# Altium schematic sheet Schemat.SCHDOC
size A4
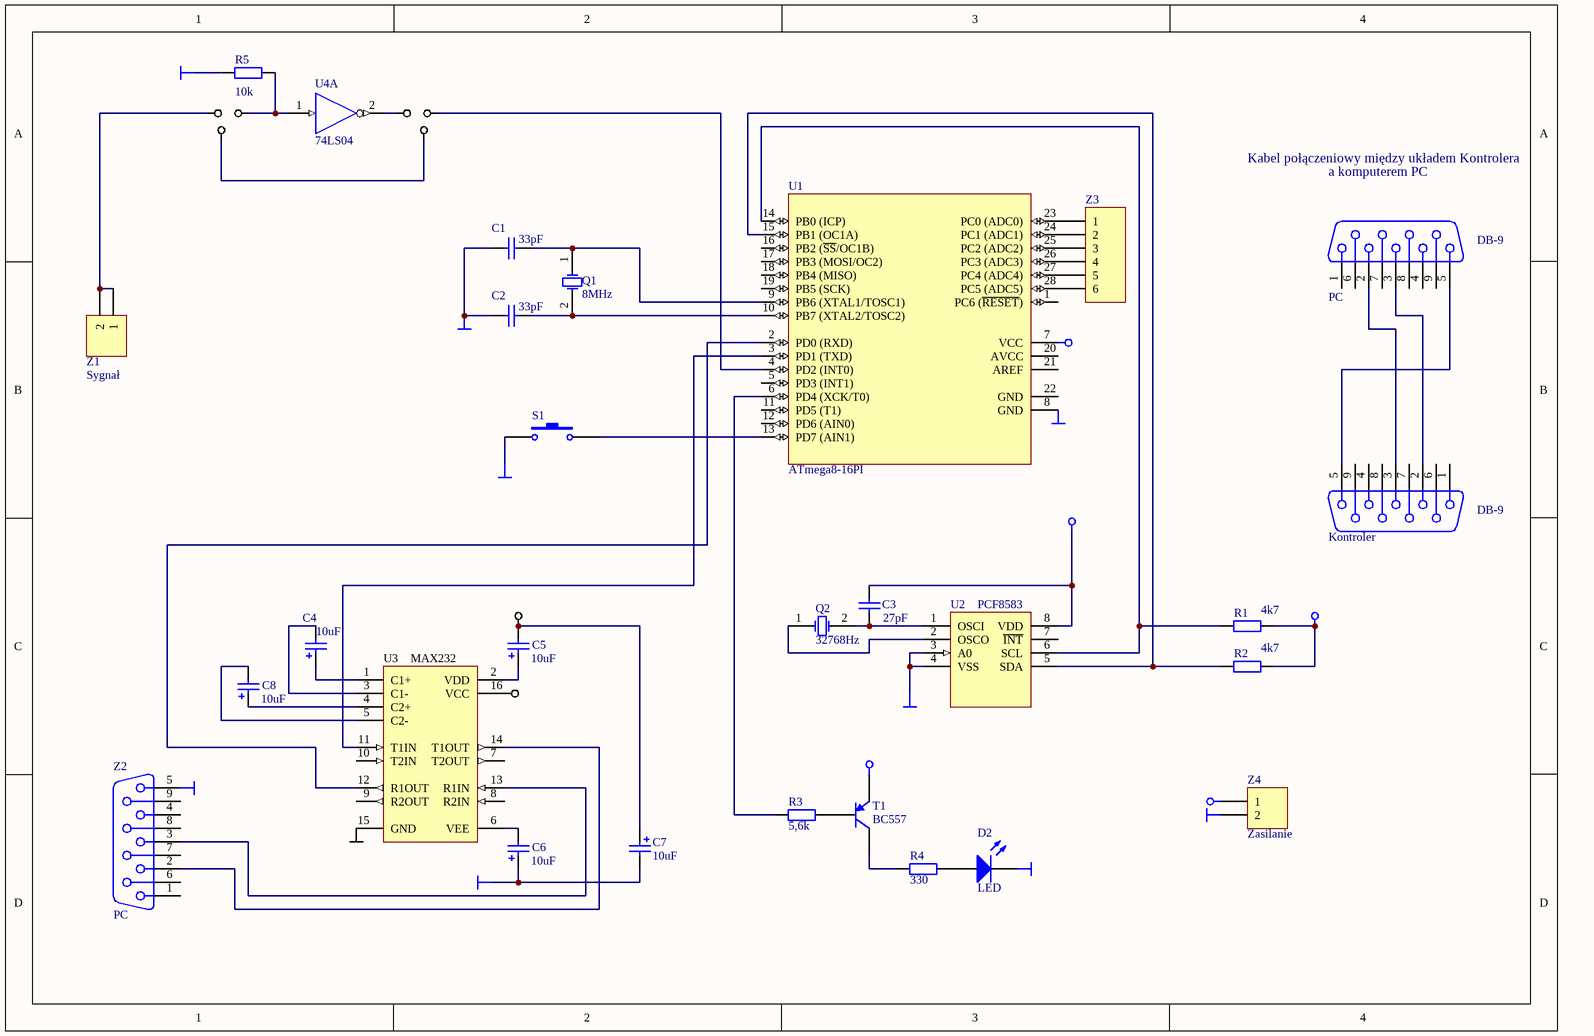
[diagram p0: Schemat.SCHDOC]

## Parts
(Parts that share a designator on the sheet are numbered #1, #2 ... from top to bottom, then left to right.)
C1  value 33pF  [RAD-0.1]  (hidden comment: Cap)
C2  value 33pF  [RAD-0.1]  (hidden comment: Cap)
C3  value 27pF  [RAD-0.1]  (hidden comment: Cap)
C4  value 10uF  [RB7.6-15]  (hidden comment: Cap Pol1)
C5  value 10uF  [RB7.6-15]  (hidden comment: Cap Pol1)
C6  value 10uF  [RB7.6-15]  (hidden comment: Cap Pol1)
C7  value 10uF  [RB7.6-15]  (hidden comment: Cap Pol1)
C8  value 10uF  [RB7.6-15]  (hidden comment: Cap Pol1)
D2  LED  [LED-0]
DB-9#1  PC  [DSUB1.385-2H9]
DB-9#2  Kontroler  [DSUB1.385-2H9]
Q1  8MHz  [BCY-W2/D3.1]
Q2  32768Hz  [BCY-W2/D3.1]
R1  value 4k7  [AXIAL-0.4]  (hidden comment: Res2)
R2  value 4k7  [AXIAL-0.4]  (hidden comment: Res2)
R3  value 5,6k  [AXIAL-0.4]  (hidden comment: Res2)
R4  value 330  [AXIAL-0.4]  (hidden comment: Res2)
R5  value 10k  [AXIAL-0.4]  (hidden comment: Res2)
S1  SW-PB  [SPST-2]  (value not drawn)
T1  BC557  [SO-G3/C2.5]
U1  ATmega8-16PI  [28P3]
U2  PCF8583  [DIP-8/D11]
U3  MAX232  [DIP-16/D21.7]
U4  74LS04  [N014]  (part A of 6)
Z1  Sygnał  [HDR1X2]
Z2  PC  [DSUB1.385-2H9]
Z3  Header 6  [HDR1X6]  (value not drawn)
Z4  Zasilanie  [HDR1X2]

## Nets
+5V: C3.2 C5.2 C7.1 R1.2 R2.2 T1.3(E) U1.7(VCC) U2.8(VDD) U3.16(VCC) Z4.1
GND: C1.1 C2.1 C6.1 C7.2 D2.2(K) R5.1 S1.1 U1.8(GND) U2.3(A0) U2.4(VSS) U4.7(GND) Z2.5 Z4.2
NetR5_2: R5.2 U1.4(PD2_(INT0)) U3.15(GND) U4.1(A) U4.2(Y) Z1.1 Z1.2
VCC: U4.14(VCC)
NetC1_2: C1.2 Q1.1(OSC1) U1.9(PB6_(XTAL1/TOSC1))
NetC2_2: C2.2 Q1.2(OSC2) U1.10(PB7_(XTAL2/TOSC2))
NetC3_1: C3.1 Q2.2(OSC2) U2.1(OSCI)
NetC4_1: C4.1 U3.1(C1+)
NetC4_2: C4.2 U3.3(C1-)
NetC5_1: C5.1 U3.2(VDD)
NetC6_2: C6.2 U3.6(VEE)
NetC8_1: C8.1 U3.4(C2+)
NetC8_2: C8.2 U3.5(C2-)
NetD2_1: D2.1(A) R4.2
NetDB-9#1_2: DB-9#1.2 DB-9#2.3
NetDB-9#1_3: DB-9#1.3 DB-9#2.2
NetDB-9#1_5: DB-9#1.5 DB-9#2.5
NetQ2_1: Q2.1(OSC1) U2.2(OSCO)
NetR1_1: R1.1 U1.14(PB0_(ICP)) U2.6(SCL)
NetR2_1: R2.1 U1.15(PB1_(OC1A)) U2.5(SDA)
NetR3_1: R3.1 U1.6(PD4_(XCK/T0))
NetR3_2: R3.2 T1.2(B)
NetR4_1: R4.1 T1.1(C)
NetS1_2: S1.2 U1.13(PD7_(AIN1))
NetU1_2: U1.2(PD0_(RXD)) U3.12(R1OUT)
NetU1_3: U1.3(PD1_(TXD)) U3.11(T1IN)
NetU1_23: U1.23(PC0_(ADC0)) Z3.1
NetU1_24: U1.24(PC1_(ADC1)) Z3.2
NetU1_25: U1.25(PC2_(ADC2)) Z3.3
NetU1_26: U1.26(PC3_(ADC3)) Z3.4
NetU1_27: U1.27(PC4_(ADC4)) Z3.5
NetU1_28: U1.28(PC5_(ADC5)) Z3.6
NetU3_13: U3.13(R1IN) Z2.3
NetU3_14: U3.14(T1OUT) Z2.2

Not connected (* = marked no-connect by the designer): DB-9#1 1 4 6 7 8 9 10(MH1) 11(MH2); DB-9#2 1 4 6 7 8 9 10(MH1) 11(MH2); U1 1(PC6_(~{RESET})) 5(PD3_(INT1)) 11(PD5_(T1)) 12(PD6_(AIN0)) 16(PB2_(~{SS}/OC1B)) 17(PB3_(MOSI/OC2)) 18(PB4_(MISO)) 19(PB5_(SCK)) 20(AVCC) 21(AREF) 22(GND); U2 7(~{INT}); U3 7(T2OUT) 8(R2IN) 9(R2OUT) 10(T2IN); Z2 1 4 6 7 8 9 10(MH1) 11(MH2)

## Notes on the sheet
- Kabel połączeniowy między układem Kontrolera
- a komputerem PC

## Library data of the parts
C1-C3 = Cap: Capacitor; Manufacturer: Generic Components; Class I: Passive
C4-C8 = Cap Pol1: Polarized Capacitor (Radial)
D2 = LED0: Typical INFRARED GaAs LED
DB-9#1 DB-9#2 Z2 = D Connector 9: Receptacle Assembly, 9 Position, Right Angle; Package Information: Latest Revision: O; Positions: 9
Q1 Q2 = XTAL: Crystal Oscillator; Manufacturer: Generic Components
R1 R2 R5 = Res2: Resistor; Manufacturer: Generic Components; Class I: Passive
R3 R4 = Res2: Resistor
S1 = SW-PB: Switch
T1 = PNP: PNP Bipolar Transistor; Code - JEDEC: SOT-23
U1 = ATmega8-16PI: 8-Bit AVR Microcontroller with 8K Bytes of In-System Programmable Flash Memory; Package Information: Latest Revision: revB, Sep-2001
U2 = REF198GP: Precision Micropower, Low-Dropout, Voltage Reference; Manufacturer: Analog Devices; Revision 1: 10-July-2000: SIM Model Added.; Revision 2: July-2002: Re-released for DXP Platform.; Class I: Power Management; Note: Pins 7 and 8 are not connected; Pins 1 and 5 are factory test only, make no electrical connection
U3 = MAX232MJE: +5V Powered RS-232 Driver/Receiver; Manufacturer: Maxim; Class I: Communication; Class II: Transceiver
U4 = SN74LS04N: Hex Inverter; Package Information: Latest Revision: Oct-1995
Z1 Z4 = Header 2: Header, 2-Pin
Z3 = Header 6: Header, 6-Pin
